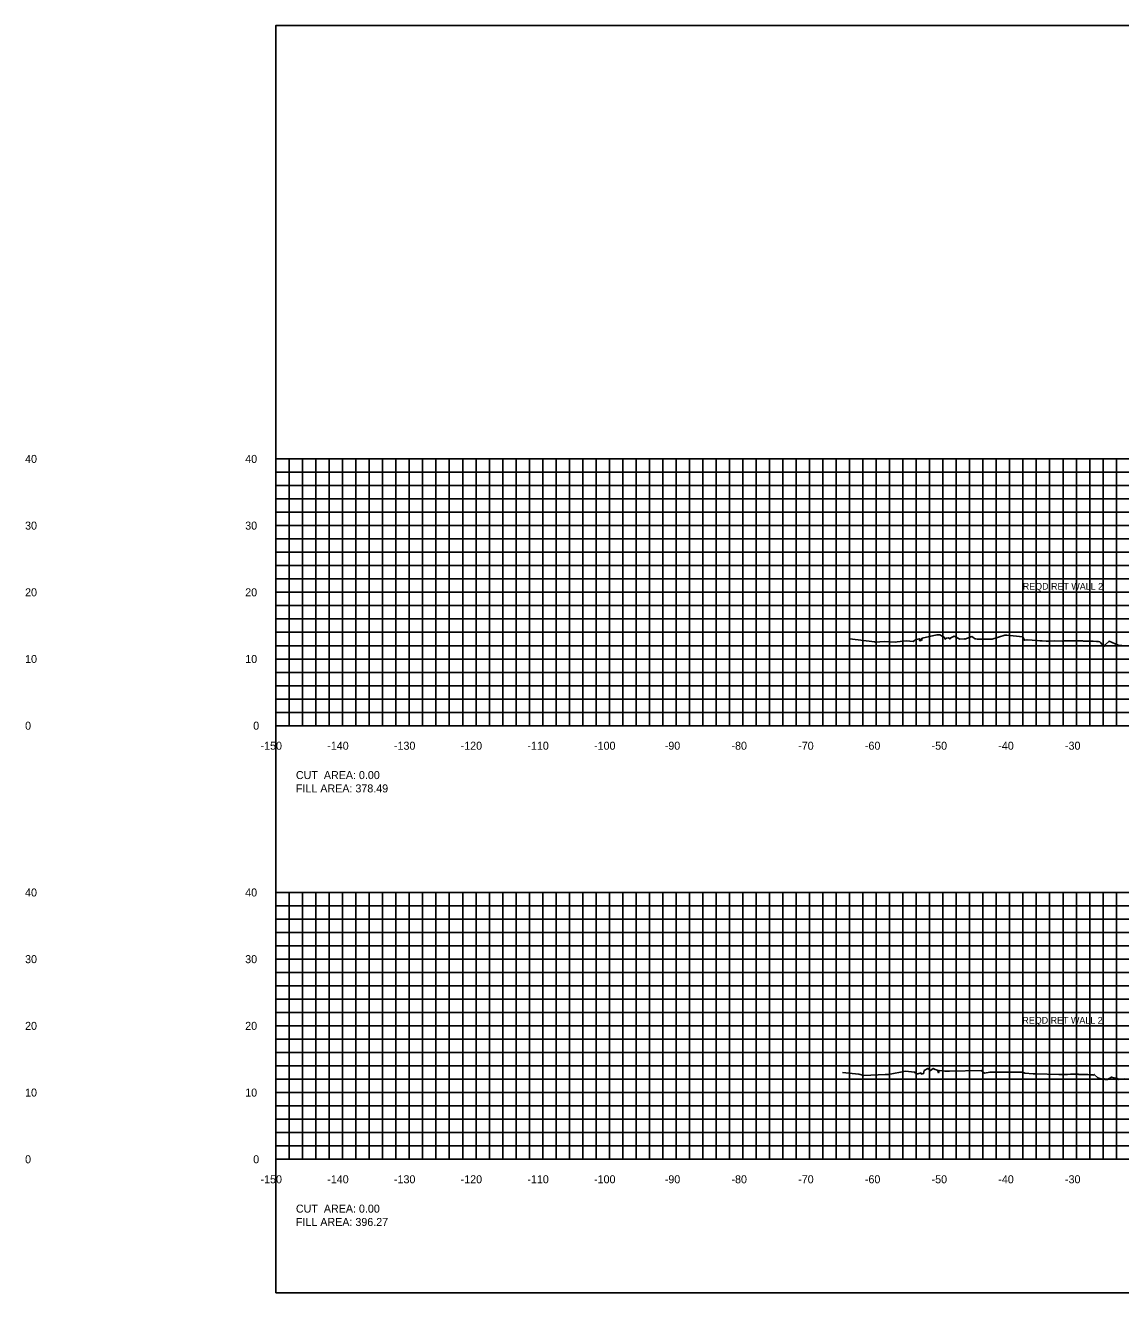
# Model space of a CAD drawing. Extents: x 1797518 to 1804843, y 248068 to 251132.
# Drawn here: x 1803463.4 to 1803627.6, y 250079.4 to 250269.4 of the extents above; entities that cross this region are included whole.
import ezdxf

# ---------------------------------------------------------------- set-up
doc = ezdxf.new("R2010")
doc.units = 0
for name, color, linetype in [('10', 7, 'Continuous'), ('3', 7, 'Continuous'), ('31', 7, 'Continuous'), ('60', 7, 'Continuous'), ('ANNO-TXT', 7, 'Continuous'), ('Level 62', 7, 'Continuous'), ('M-ROADS', 7, 'Continuous')]:
    doc.layers.add(name, color=color, linetype=linetype)

msp = doc.modelspace()

# ---------------------------------------------------------------- linework, layer by layer
msp.add_lwpolyline([(1803501, 250079.43), (1803801, 250079.43), (1803801, 250269.43), (1803501, 250269.43)], close=True)
at = {"layer": '60'}
for p, q in [((1803500.94, 250204.43), (1803501, 250204.43)), ((1803501, 250164.43), (1803501, 250204.43)), ((1803500.94, 250194.43), (1803501, 250194.43)), ((1803500.94, 250184.43), (1803501, 250184.43)), ((1803500.94, 250174.43), (1803501, 250174.43)), ((1803500.94, 250164.43), (1803501, 250164.43)), ((1803501, 250164.43), (1803801, 250164.43)), ((1803501, 250164.37), (1803501, 250164.43)), ((1803511, 250164.37), (1803511, 250164.43)), ((1803521, 250164.37), (1803521, 250164.43)), ((1803531, 250164.37), (1803531, 250164.43)), ((1803541, 250164.37), (1803541, 250164.43)), ((1803551, 250164.37), (1803551, 250164.43)), ((1803561, 250164.37), (1803561, 250164.43)), ((1803571, 250164.37), (1803571, 250164.43)), ((1803581, 250164.37), (1803581, 250164.43)), ((1803591, 250164.37), (1803591, 250164.43)), ((1803601, 250164.37), (1803601, 250164.43)), ((1803611, 250164.37), (1803611, 250164.43)), ((1803621, 250164.37), (1803621, 250164.43)), ((1803500.94, 250139.43), (1803501, 250139.43)), ((1803501, 250099.43), (1803501, 250139.43)), ((1803500.94, 250129.43), (1803501, 250129.43)), ((1803500.94, 250119.43), (1803501, 250119.43)), ((1803500.94, 250109.43), (1803501, 250109.43)), ((1803500.94, 250099.43), (1803501, 250099.43)), ((1803501, 250099.43), (1803801, 250099.43)), ((1803501, 250099.37), (1803501, 250099.43)), ((1803511, 250099.37), (1803511, 250099.43)), ((1803521, 250099.37), (1803521, 250099.43)), ((1803531, 250099.37), (1803531, 250099.43)), ((1803541, 250099.37), (1803541, 250099.43)), ((1803551, 250099.37), (1803551, 250099.43)), ((1803561, 250099.37), (1803561, 250099.43)), ((1803571, 250099.37), (1803571, 250099.43)), ((1803581, 250099.37), (1803581, 250099.43)), ((1803591, 250099.37), (1803591, 250099.43)), ((1803601, 250099.37), (1803601, 250099.43)), ((1803611, 250099.37), (1803611, 250099.43)), ((1803621, 250099.37), (1803621, 250099.43))]:
    msp.add_line(p, q, dxfattribs=at)
at = {"layer": 'Level 62'}
for p, q in [((1803501, 250204.43), (1803801, 250204.43)), ((1803501, 250164.43), (1803501, 250204.43)), ((1803503, 250164.43), (1803503, 250204.43)), ((1803505, 250164.43), (1803505, 250204.43)), ((1803507, 250164.43), (1803507, 250204.43)), ((1803509, 250164.43), (1803509, 250204.43)), ((1803511, 250164.43), (1803511, 250204.43)), ((1803513, 250164.43), (1803513, 250204.43)), ((1803515, 250164.43), (1803515, 250204.43)), ((1803517, 250164.43), (1803517, 250204.43)), ((1803519, 250164.43), (1803519, 250204.43)), ((1803521, 250164.43), (1803521, 250204.43)), ((1803523, 250164.43), (1803523, 250204.43)), ((1803525, 250164.43), (1803525, 250204.43)), ((1803527, 250164.43), (1803527, 250204.43)), ((1803529, 250164.43), (1803529, 250204.43)), ((1803531, 250164.43), (1803531, 250204.43)), ((1803533, 250164.43), (1803533, 250204.43)), ((1803535, 250164.43), (1803535, 250204.43)), ((1803537, 250164.43), (1803537, 250204.43)), ((1803539, 250164.43), (1803539, 250204.43)), ((1803541, 250164.43), (1803541, 250204.43)), ((1803543, 250164.43), (1803543, 250204.43)), ((1803545, 250164.43), (1803545, 250204.43)), ((1803547, 250164.43), (1803547, 250204.43)), ((1803549, 250164.43), (1803549, 250204.43)), ((1803551, 250164.43), (1803551, 250204.43)), ((1803553, 250164.43), (1803553, 250204.43)), ((1803555, 250164.43), (1803555, 250204.43)), ((1803557, 250164.43), (1803557, 250204.43)), ((1803559, 250164.43), (1803559, 250204.43)), ((1803561, 250164.43), (1803561, 250204.43)), ((1803563, 250164.43), (1803563, 250204.43)), ((1803565, 250164.43), (1803565, 250204.43)), ((1803567, 250164.43), (1803567, 250204.43)), ((1803569, 250164.43), (1803569, 250204.43)), ((1803571, 250164.43), (1803571, 250204.43)), ((1803573, 250164.43), (1803573, 250204.43)), ((1803575, 250164.43), (1803575, 250204.43)), ((1803577, 250164.43), (1803577, 250204.43)), ((1803579, 250164.43), (1803579, 250204.43)), ((1803581, 250164.43), (1803581, 250204.43)), ((1803583, 250164.43), (1803583, 250204.43)), ((1803585, 250164.43), (1803585, 250204.43)), ((1803587, 250164.43), (1803587, 250204.43)), ((1803589, 250164.43), (1803589, 250204.43)), ((1803591, 250164.43), (1803591, 250204.43)), ((1803593, 250164.43), (1803593, 250204.43)), ((1803595, 250164.43), (1803595, 250204.43)), ((1803597, 250164.43), (1803597, 250204.43)), ((1803599, 250164.43), (1803599, 250204.43)), ((1803601, 250164.43), (1803601, 250204.43)), ((1803603, 250164.43), (1803603, 250204.43)), ((1803605, 250164.43), (1803605, 250204.43)), ((1803607, 250164.43), (1803607, 250204.43)), ((1803609, 250164.43), (1803609, 250204.43)), ((1803611, 250164.43), (1803611, 250204.43)), ((1803613, 250164.43), (1803613, 250204.43)), ((1803615, 250164.43), (1803615, 250204.43)), ((1803617, 250164.43), (1803617, 250204.43)), ((1803619, 250164.43), (1803619, 250204.43)), ((1803621, 250164.43), (1803621, 250204.43)), ((1803623, 250164.43), (1803623, 250204.43)), ((1803625, 250164.43), (1803625, 250204.43)), ((1803627, 250164.43), (1803627, 250204.43)), ((1803501, 250202.43), (1803801, 250202.43)), ((1803501, 250200.43), (1803801, 250200.43)), ((1803501, 250198.43), (1803801, 250198.43)), ((1803501, 250196.43), (1803801, 250196.43)), ((1803501, 250194.43), (1803801, 250194.43)), ((1803501, 250192.43), (1803801, 250192.43)), ((1803501, 250190.43), (1803801, 250190.43)), ((1803501, 250188.43), (1803801, 250188.43)), ((1803501, 250186.43), (1803801, 250186.43)), ((1803501, 250184.43), (1803801, 250184.43)), ((1803501, 250182.43), (1803801, 250182.43)), ((1803501, 250180.43), (1803801, 250180.43)), ((1803501, 250178.43), (1803801, 250178.43)), ((1803501, 250176.43), (1803801, 250176.43)), ((1803501, 250174.43), (1803801, 250174.43)), ((1803501, 250172.43), (1803801, 250172.43)), ((1803501, 250170.43), (1803801, 250170.43)), ((1803501, 250168.43), (1803801, 250168.43)), ((1803501, 250166.43), (1803801, 250166.43)), ((1803501, 250164.43), (1803801, 250164.43)), ((1803501, 250139.43), (1803801, 250139.43)), ((1803501, 250099.43), (1803501, 250139.43)), ((1803503, 250099.43), (1803503, 250139.43)), ((1803505, 250099.43), (1803505, 250139.43)), ((1803507, 250099.43), (1803507, 250139.43)), ((1803509, 250099.43), (1803509, 250139.43)), ((1803511, 250099.43), (1803511, 250139.43)), ((1803513, 250099.43), (1803513, 250139.43)), ((1803515, 250099.43), (1803515, 250139.43)), ((1803517, 250099.43), (1803517, 250139.43)), ((1803519, 250099.43), (1803519, 250139.43)), ((1803521, 250099.43), (1803521, 250139.43)), ((1803523, 250099.43), (1803523, 250139.43)), ((1803525, 250099.43), (1803525, 250139.43)), ((1803527, 250099.43), (1803527, 250139.43)), ((1803529, 250099.43), (1803529, 250139.43)), ((1803531, 250099.43), (1803531, 250139.43)), ((1803533, 250099.43), (1803533, 250139.43)), ((1803535, 250099.43), (1803535, 250139.43)), ((1803537, 250099.43), (1803537, 250139.43)), ((1803539, 250099.43), (1803539, 250139.43)), ((1803541, 250099.43), (1803541, 250139.43)), ((1803543, 250099.43), (1803543, 250139.43)), ((1803545, 250099.43), (1803545, 250139.43)), ((1803547, 250099.43), (1803547, 250139.43)), ((1803549, 250099.43), (1803549, 250139.43)), ((1803551, 250099.43), (1803551, 250139.43)), ((1803553, 250099.43), (1803553, 250139.43)), ((1803555, 250099.43), (1803555, 250139.43)), ((1803557, 250099.43), (1803557, 250139.43)), ((1803559, 250099.43), (1803559, 250139.43)), ((1803561, 250099.43), (1803561, 250139.43)), ((1803563, 250099.43), (1803563, 250139.43)), ((1803565, 250099.43), (1803565, 250139.43)), ((1803567, 250099.43), (1803567, 250139.43)), ((1803569, 250099.43), (1803569, 250139.43)), ((1803571, 250099.43), (1803571, 250139.43)), ((1803573, 250099.43), (1803573, 250139.43)), ((1803575, 250099.43), (1803575, 250139.43)), ((1803577, 250099.43), (1803577, 250139.43)), ((1803579, 250099.43), (1803579, 250139.43)), ((1803581, 250099.43), (1803581, 250139.43)), ((1803583, 250099.43), (1803583, 250139.43)), ((1803585, 250099.43), (1803585, 250139.43)), ((1803587, 250099.43), (1803587, 250139.43)), ((1803589, 250099.43), (1803589, 250139.43)), ((1803591, 250099.43), (1803591, 250139.43)), ((1803593, 250099.43), (1803593, 250139.43)), ((1803595, 250099.43), (1803595, 250139.43)), ((1803597, 250099.43), (1803597, 250139.43)), ((1803599, 250099.43), (1803599, 250139.43)), ((1803601, 250099.43), (1803601, 250139.43)), ((1803603, 250099.43), (1803603, 250139.43)), ((1803605, 250099.43), (1803605, 250139.43)), ((1803607, 250099.43), (1803607, 250139.43)), ((1803609, 250099.43), (1803609, 250139.43)), ((1803611, 250099.43), (1803611, 250139.43)), ((1803613, 250099.43), (1803613, 250139.43)), ((1803615, 250099.43), (1803615, 250139.43)), ((1803617, 250099.43), (1803617, 250139.43)), ((1803619, 250099.43), (1803619, 250139.43)), ((1803621, 250099.43), (1803621, 250139.43)), ((1803623, 250099.43), (1803623, 250139.43)), ((1803625, 250099.43), (1803625, 250139.43)), ((1803627, 250099.43), (1803627, 250139.43)), ((1803501, 250137.43), (1803801, 250137.43)), ((1803501, 250135.43), (1803801, 250135.43)), ((1803501, 250133.43), (1803801, 250133.43)), ((1803501, 250131.43), (1803801, 250131.43)), ((1803501, 250129.43), (1803801, 250129.43)), ((1803501, 250127.43), (1803801, 250127.43)), ((1803501, 250125.43), (1803801, 250125.43)), ((1803501, 250123.43), (1803801, 250123.43)), ((1803501, 250121.43), (1803801, 250121.43)), ((1803501, 250119.43), (1803801, 250119.43)), ((1803501, 250117.43), (1803801, 250117.43)), ((1803501, 250115.43), (1803801, 250115.43)), ((1803501, 250113.43), (1803801, 250113.43)), ((1803501, 250111.43), (1803801, 250111.43)), ((1803501, 250109.43), (1803801, 250109.43)), ((1803501, 250107.43), (1803801, 250107.43)), ((1803501, 250105.43), (1803801, 250105.43)), ((1803501, 250103.43), (1803801, 250103.43)), ((1803501, 250101.43), (1803801, 250101.43)), ((1803501, 250099.43), (1803801, 250099.43))]:
    msp.add_line(p, q, dxfattribs=at)
at = {"layer": 'M-ROADS'}
for points in [[(1803587.05, 250177.44), (1803590.76, 250177.01), (1803590.9, 250176.97), (1803592.21, 250177.05), (1803593.83, 250176.98), (1803594.13, 250177.03), (1803595.55, 250177.16), (1803596.53, 250177.08), (1803596.75, 250177.21), (1803596.84, 250177.29), (1803597.46, 250177.48), (1803597.52, 250177.16), (1803597.7, 250177.21), (1803597.73, 250177.19), (1803597.75, 250177.5), (1803597.76, 250177.25), (1803597.78, 250177.23), (1803597.89, 250177.56), (1803600.07, 250178.05), (1803600.52, 250178.05), (1803600.88, 250177.87), (1803601.18, 250177.73), (1803601.26, 250177.6), (1803601.29, 250177.5), (1803601.3, 250177.42), (1803601.51, 250177.57), (1803601.81, 250177.62), (1803602.04, 250177.48), (1803602.07, 250177.44), (1803602.08, 250177.55), (1803602.67, 250177.86), (1803603.53, 250177.43), (1803604.2, 250177.45), (1803604.3, 250177.42), (1803605.31, 250177.79), (1803605.88, 250177.43), (1803605.89, 250177.43), (1803605.91, 250177.47), (1803606.12, 250177.43), (1803608.4, 250177.43), (1803610.28, 250177.99), (1803610.58, 250178), (1803612.98, 250177.78), (1803613.25, 250177.25), (1803613.62, 250177.32), (1803615.15, 250177.23), (1803615.55, 250177.17), (1803615.71, 250177.16), (1803615.89, 250177.15), (1803616.46, 250177.13), (1803616.79, 250177.13), (1803617.06, 250177.13), (1803617.75, 250177.17), (1803618.89, 250177.13), (1803619.03, 250177.15), (1803621.97, 250177.16), (1803622.03, 250177.1), (1803623.17, 250177.13), (1803623.22, 250177.13), (1803623.4, 250177.12), (1803623.54, 250177.1), (1803624.04, 250177.07), (1803624.11, 250177.04), (1803624.34, 250177.05), (1803624.51, 250177.03), (1803624.61, 250176.92), (1803624.72, 250176.78), (1803625.22, 250176.34), (1803625.24, 250176.4), (1803625.34, 250176.54), (1803625.9, 250177.12), (1803627.25, 250176.53), (1803627.8, 250176.44)], [(1803585.94, 250112.46), (1803588.4, 250112.17), (1803589.14, 250111.97), (1803592.33, 250112.16), (1803592.83, 250112.15), (1803595.37, 250112.62), (1803596.76, 250112.49), (1803597.04, 250112.24), (1803597.07, 250112.24), (1803597.18, 250112.24), (1803597.26, 250112.24), (1803597.72, 250112.38), (1803597.75, 250112.2), (1803597.89, 250112.24), (1803598.07, 250112.27), (1803598.09, 250112.26), (1803598.1, 250112.41), (1803598.11, 250112.28), (1803598.21, 250112.73), (1803598.73, 250113.05), (1803599.15, 250112.72), (1803599.55, 250113.05), (1803599.84, 250112.88), (1803600.17, 250112.81), (1803600.33, 250112.41), (1803600.41, 250112.76), (1803601.29, 250112.62), (1803601.98, 250112.66), (1803606.75, 250112.73), (1803607.23, 250112.34), (1803608.04, 250112.49), (1803608.08, 250112.49), (1803610.44, 250112.49), (1803612.81, 250112.49), (1803612.94, 250112.49), (1803613.26, 250112.33), (1803614.53, 250112.26), (1803614.74, 250112.23), (1803614.82, 250112.22), (1803614.92, 250112.22), (1803618.35, 250112.13), (1803618.53, 250112.13), (1803618.68, 250112.13), (1803619.04, 250112.15), (1803619.66, 250112.13), (1803620.13, 250112.2), (1803621.25, 250112.2), (1803621.35, 250112.12), (1803621.96, 250112.13), (1803622.74, 250112.13), (1803622.96, 250112.07), (1803623.29, 250112.08), (1803623.54, 250112.08), (1803623.61, 250112.06), (1803623.68, 250112.15), (1803624.21, 250111.64), (1803624.89, 250111.46), (1803624.94, 250111.41), (1803625.06, 250111.53), (1803625.31, 250111.41), (1803625.68, 250111.41), (1803626.29, 250111.74), (1803627.12, 250111.52), (1803627.36, 250111.41), (1803628.2, 250111.5)]]:
    msp.add_lwpolyline(points, dxfattribs=at)

# ---------------------------------------------------------------- texts
at = {"layer": '10'}
for s, p in [('-150', (1803498.7, 250160.83)), ('-140', (1803508.7, 250160.83)), ('-130', (1803518.7, 250160.83)), ('-120', (1803528.7, 250160.83)), ('-110', (1803538.7, 250160.83)), ('-100', (1803548.7, 250160.83)), ('-90', (1803559.3, 250160.83)), ('-80', (1803569.3, 250160.83)), ('-70', (1803579.3, 250160.83)), ('-60', (1803589.3, 250160.83)), ('-50', (1803599.3, 250160.83)), ('-40', (1803609.3, 250160.83)), ('-30', (1803619.3, 250160.83)), ('-150', (1803498.7, 250095.83)), ('-140', (1803508.7, 250095.83)), ('-130', (1803518.7, 250095.83)), ('-120', (1803528.7, 250095.83)), ('-110', (1803538.7, 250095.83)), ('-100', (1803548.7, 250095.83)), ('-90', (1803559.3, 250095.83)), ('-80', (1803569.3, 250095.83)), ('-70', (1803579.3, 250095.83)), ('-60', (1803589.3, 250095.83)), ('-50', (1803599.3, 250095.83)), ('-40', (1803609.3, 250095.83)), ('-30', (1803619.3, 250095.83))]:
    msp.add_text(s, height=1.2, dxfattribs=at).set_placement(p)
at = {"layer": '3'}
for p in [(1803612.97, 250184.83), (1803612.91, 250119.77)]:
    msp.add_text('REQD RET WALL 2', height=1, dxfattribs=at).set_placement(p)
at = {"layer": '31'}
for s, p in [('40', (1803463.4, 250203.83)), ('40', (1803496.4, 250203.83)), ('30', (1803463.4, 250193.83)), ('30', (1803496.4, 250193.83)), ('20', (1803463.4, 250183.83)), ('20', (1803496.4, 250183.83)), ('10', (1803463.4, 250173.83)), ('10', (1803496.4, 250173.83)), ('0', (1803463.4, 250163.83)), ('0', (1803497.6, 250163.83)), ('40', (1803463.4, 250138.83)), ('40', (1803496.4, 250138.83)), ('30', (1803463.4, 250128.83)), ('30', (1803496.4, 250128.83)), ('20', (1803463.4, 250118.83)), ('20', (1803496.4, 250118.83)), ('10', (1803463.4, 250108.83)), ('10', (1803496.4, 250108.83)), ('0', (1803463.4, 250098.83)), ('0', (1803497.6, 250098.83))]:
    msp.add_text(s, height=1.2, dxfattribs=at).set_placement(p)
at = {"layer": '60'}
for p in [(1803501, 250164.43), (1803501, 250099.43)]:
    msp.add_text('-', height=0.0001, dxfattribs=at).set_placement(p)
at = {"layer": 'ANNO-TXT'}
for s, p in [('CUT  AREA: 0.00', (1803504, 250156.43)), ('FILL AREA: 378.49', (1803504, 250154.43)), ('CUT  AREA: 0.00', (1803504, 250091.43)), ('FILL AREA: 396.27', (1803504, 250089.43))]:
    msp.add_text(s, height=1.2, dxfattribs=at).set_placement(p)

doc.saveas('drawing.dxf')
